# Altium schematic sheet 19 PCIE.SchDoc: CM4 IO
size 297 x 209 mm; Page Create Date: March  8, 1995; Page Number: 19; Page Size: A4; Comment: radxa_1010; Page Count: 19; RevCode: V1.10; Doc: 19 PCIE; DsnPath: D:\WMS\黄工\[RC126]CM4_IO_V1.10\[RC126]_V1.10\CM4 IO_V1.10.DSN; SchematicName: CM4 IO V1.10; PageName: 19 PCIE; PageSize: A4; TopSchematic: True
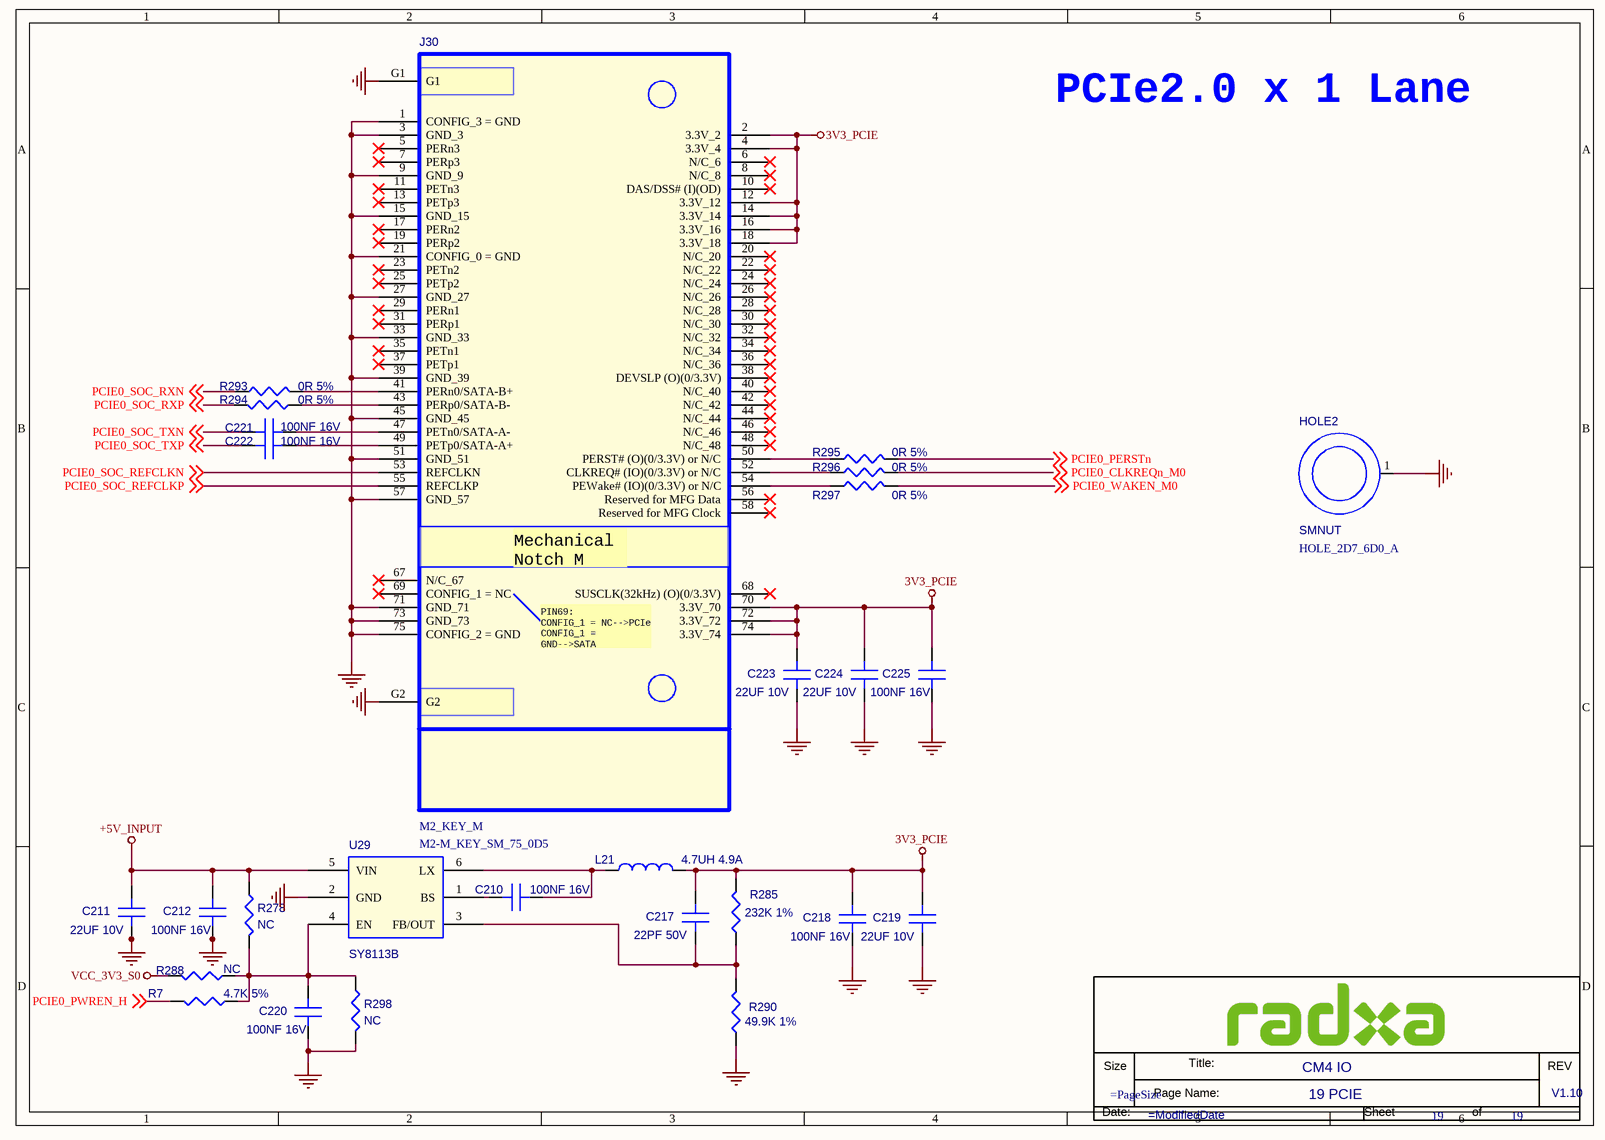
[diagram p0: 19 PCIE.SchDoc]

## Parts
*  Doc: 19 PCIE  RevCode: V1.10  Title: CM4 IO  Page Number: 19  (hidden comment: radxa_1010)  (graphical)
C210  100NF 16V  [C0201]
C211  22UF 10V  [C0603]
C212  100NF 16V  [C0201]
C217  22PF 50V  [C0201]
C218  100NF 16V  [C0201]
C219  22UF 10V  [C0603]
C220  100NF 16V  [C0201]
C221  100NF 16V  [C0201]
C222  100NF 16V  [C0201]
C223  22UF 10V  [C0603]
C224  22UF 10V  [C0603]
C225  100NF 16V  [C0201]
HOLE2  SMNUT  [HOLE_2D7_6D0_A]
J30  M2_KEY_M  [M2-M_KEY_SM_75_0D5]
L21  4.7UH 4.9A  [L_4020]
R7  4.7K 5%  [R0402]
R278  NC  [R0402]
R285  232K 1%  [R0402]
R288  NC  [R0402]
R290  49.9K 1%  [R0402]
R293  0R 5%  [R0402]
R294  0R 5%  [R0402]
R295  0R 5%  [R0402]
R296  0R 5%  [R0402]
R297  0R 5%  [R0402]
R298  NC  [R0402]
U29  SY8113B  [SOT23_6]

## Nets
3V3_PCIE: C217.1(A) C218.1(A) C219.1(A) C223.1(A) C224.1(A) C225.1(A) J30.2(3.3V_2) J30.4(3.3V_4) J30.12(3.3V_12) J30.14(3.3V_14) J30.16(3.3V_16) J30.18(3.3V_18) J30.70(3.3V_70) J30.72(3.3V_72) J30.74(3.3V_74) L21.2 R285.1
+5V_INPUT: C211.1(A) C212.1(A) R278.2 U29.5(VIN)
GND: C211.2(B) C212.2(B) C218.2(B) C219.2(B) C220.2(B) C223.2(B) C224.2(B) C225.2(B) HOLE2.1 J30.1(CONFIG_3_=_GND) J30.3(GND_3) J30.9(GND_9) J30.15(GND_15) J30.21(CONFIG_0_=_GND) J30.27(GND_27) J30.33(GND_33) J30.39(GND_39) J30.45(GND_45) J30.51(GND_51) J30.57(GND_57) J30.71(GND_71) J30.73(GND_73) J30.75(CONFIG_2_=_GND) J30.G1 J30.G2 R290.2 R298.1 U29.2(GND)
VCC_3V3_S0: R288.1
PCIE0_CLKREQn_M0: R296.2 ; off-sheet PCIE0_CLKREQn_M0
PCIE0_PERSTn: R295.2 ; off-sheet PCIE0_PERSTn
PCIE0_PWREN_H: R7.1 ; off-sheet PCIE0_PWREN_H
PCIE0_SOC_REFCLKN: J30.53(REFCLKN) ; off-sheet PCIE0_SOC_REFCLKN
PCIE0_SOC_REFCLKP: J30.55(REFCLKP) ; off-sheet PCIE0_SOC_REFCLKP
PCIE0_SOC_RXN: R293.1 ; off-sheet PCIE0_SOC_RXN
PCIE0_SOC_RXP: R294.1 ; off-sheet PCIE0_SOC_RXP
PCIE0_SOC_TXN: C221.1(A) ; off-sheet PCIE0_SOC_TXN
PCIE0_SOC_TXP: C222.1(A) ; off-sheet PCIE0_SOC_TXP
PCIE0_WAKEN_M0: R297.2 ; off-sheet PCIE0_WAKEN_M0
NetC210_1: C210.1(A) U29.1(BS)
NetC210_2: C210.2(B) L21.1 U29.6(LX)
NetC217_2: C217.2(B) R285.2 R290.1 U29.3(FB/OUT)
NetC220_1: C220.1(A) R7.2 R278.1 R288.2 R298.2 U29.4(EN)
NetC221_2: C221.2(B) J30.47(PETn0/SATA-A-)
NetC222_2: C222.2(B) J30.49(PETp0/SATA-A+)
NetJ30_41: J30.41(PERn0/SATA-B+) R293.2
NetJ30_43: J30.43(PERp0/SATA-B-) R294.2
NetJ30_50: J30.50(PERST#_(O)(0/3.3V)_or_N/C) R295.1
NetJ30_52: J30.52(CLKREQ#_(IO)(0/3.3V)_or_N/C) R296.1
NetJ30_54: J30.54(PEWake#_(IO)(0/3.3V)_or_N/C) R297.1

Not connected (* = marked no-connect by the designer): J30 5(PERn3)* 6(N/C_6)* 7(PERp3)* 8(N/C_8)* 10(DAS/DSS#_(I)(OD))* 11(PETn3)* 13(PETp3)* 17(PERn2)* 19(PERp2)* 20(N/C_20)* 22(N/C_22)* 23(PETn2)* 24(N/C_24)* 25(PETp2)* 26(N/C_26)* 28(N/C_28)* 29(PERn1)* 30(N/C_30)* 31(PERp1)* 32(N/C_32)* 34(N/C_34)* 35(PETn1)* 36(N/C_36)* 37(PETp1)* 38(DEVSLP_(O)(0/3.3V))* 40(N/C_40)* 42(N/C_42)* 44(N/C_44)* 46(N/C_46)* 48(N/C_48)* 56(Reserved_for_MFG_Data)* 58(Reserved_for_MFG_Clock)* 67(N/C_67)* 68(SUSCLK(32kHz)_(O)(0/3.3V))* 69(CONFIG_1_=_NC)*

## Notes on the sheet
- PCIe2.0 x 1 Lane

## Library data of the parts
C210 = C: SMD  0201  100NF  16V  X5R  ±20%  ROHS; PARTS: 1; Part Reference: C210; Part Number: A1C01.00099; OriginalSymbolOrigin: (0,30); PKG_TYPE: CAP2-100-250; LEVEL: STD; PINSWAP: (A,B); Preferred: 6715f349cd0bc5
C211 = C: SMD  0603  22UF  10V  X5R  ±10%  ROHS; PARTS: 1; Part Reference: C211; Part Number: A1C01.00296; OriginalSymbolOrigin: (0,30); PKG_TYPE: CAP2-100-250; LEVEL: STD; PINSWAP: (A,B)
C212 = C: SMD  0201  100NF  16V  X5R  ±20%  ROHS; PARTS: 1; Part Reference: C212; Part Number: A1C01.00099; OriginalSymbolOrigin: (0,30); PKG_TYPE: CAP2-100-250; LEVEL: STD; PINSWAP: (A,B); Preferred: 6715f349cd0bc5
C217 = C: SMD  0201  22PF  50V  NPO  ±5%  ROHS; PARTS: 1; Part Reference: C217; Part Number: A1C01.00021; OriginalSymbolOrigin: (0,30); PKG_TYPE: CAP2-100-250; LEVEL: STD; PINSWAP: (A,B)
C218 = C: SMD  0201  100NF  16V  X5R  ±20%  ROHS; PARTS: 1; Part Reference: C218; Part Number: A1C01.00099; OriginalSymbolOrigin: (0,30); PKG_TYPE: CAP2-100-250; LEVEL: STD; PINSWAP: (A,B); Preferred: 6715f349cd0bc5
C219 = C: SMD  0603  22UF  10V  X5R  ±10%  ROHS; PARTS: 1; Part Reference: C219; Part Number: A1C01.00296; OriginalSymbolOrigin: (0,30); PKG_TYPE: CAP2-100-250; LEVEL: STD; PINSWAP: (A,B)
C220 = C: SMD  0201  100NF  16V  X5R  ±20%  ROHS; PARTS: 1; Part Reference: C220; Part Number: A1C01.00099; OriginalSymbolOrigin: (0,30); PKG_TYPE: CAP2-100-250; LEVEL: STD; PINSWAP: (A,B); Preferred: 6715f349cd0bc5
C221 = C: SMD  0201  100NF  16V  X5R  ±20%  ROHS; PARTS: 1; Part Reference: C221; Part Number: A1C01.00099; OriginalSymbolOrigin: (0,30); PKG_TYPE: CAP2-100-250; LEVEL: STD; PINSWAP: (A,B); Preferred: 6715f349cd0bc5
C222 = C: SMD  0201  100NF  16V  X5R  ±20%  ROHS; PARTS: 1; Part Reference: C222; Part Number: A1C01.00099; OriginalSymbolOrigin: (0,30); PKG_TYPE: CAP2-100-250; LEVEL: STD; PINSWAP: (A,B); Preferred: 6715f349cd0bc5
C223 = C: SMD  0603  22UF  10V  X5R  ±10%  ROHS; PARTS: 1; Part Reference: C223; Part Number: A1C01.00296; OriginalSymbolOrigin: (0,30); PKG_TYPE: CAP2-100-250; LEVEL: STD; PINSWAP: (A,B)
C224 = C: SMD  0603  22UF  10V  X5R  ±10%  ROHS; PARTS: 1; Part Reference: C224; Part Number: A1C01.00296; OriginalSymbolOrigin: (0,30); PKG_TYPE: CAP2-100-250; LEVEL: STD; PINSWAP: (A,B)
C225 = C: SMD  0201  100NF  16V  X5R  ±20%  ROHS; PARTS: 1; Part Reference: C225; Part Number: A1C01.00099; OriginalSymbolOrigin: (0,30); PKG_TYPE: CAP2-100-250; LEVEL: STD; PINSWAP: (A,B); Preferred: 6715f349cd0bc5
HOLE2 = SMNUT: SMD  编带  M2  通孔  一端?5mm  高6.6mm  另一端?2.5mm  高1.5mm  总高8.8mm  (带定位台阶φ2.5mm 高度0.7mm 贴高温胶纸)  适配H8.5高M.2座  铜  镀锡  DDSMT20241011288  ROHS; Part Reference: HOLE2; Part Number: A1S01.00008; Temp Coeff: -40℃ to +150℃; Preferred: 6715f349cd0bc5
J30 = M2_KEY_M: SMD  母座  75PIN  180度  0.5mm脚距  M.2  M KEY  H8.5  黑色  ROHS; Part Reference: J30; Part Number: A1J01.00045; Parameter: 连接器-比派-封装 M2_KEY_M
L21 = L: SMD  带屏蔽  4*4*2mm  4.7UH  4.9A  ±20%  RXWHJ4020-4R7MT  ROHS; Part Reference: L21; Part Number: A1L01.00026
R7 = R: SMD  0201  4.7K  1/20W  ±5%  ROHS; Part Reference: R7; Part Number: A1R01.00014; PCB Footprint: R0201; Preferred: 6715f349cd0bc5; Temp Coeff: -55℃ to +125℃
R278 = R: SMD  0201  10K  1/20W  ±5%  ROHS; Part Reference: R278; Part Number: A1R01.00012; PCB Footprint: R0201; Temp Coeff: －55℃ ~ ＋125℃
R285 = R: SMD  0201  232K  1/20W  ±1%  ROHS; Part Reference: R285; Part Number: A1R01.00189; PCB Footprint: R0201
R288 = R: SMD  0201  10K  1/20W  ±5%  ROHS; Part Reference: R288; Part Number: A1R01.00012; PCB Footprint: R0201; Temp Coeff: －55℃ ~ ＋125℃
R290 = R: SMD  0201  49.9K  1/20W  ±1%  ROHS; Part Reference: R290; Part Number: A1R01.00207; PCB Footprint: R0201
R293 = R: SMD  0201  0R  1/20W  ±5%  ROHS; Part Reference: R293; Part Number: A1R01.00027; PCB Footprint: R0201; Temp Coeff: －55℃ ~ ＋125℃
R294 = R: SMD  0201  0R  1/20W  ±5%  ROHS; Part Reference: R294; Part Number: A1R01.00027; PCB Footprint: R0201; Temp Coeff: －55℃ ~ ＋125℃
R295 = R: SMD  0201  0R  1/20W  ±5%  ROHS; Part Reference: R295; Part Number: A1R01.00027; PCB Footprint: R0201; Temp Coeff: －55℃ ~ ＋125℃
R296 = R: SMD  0201  0R  1/20W  ±5%  ROHS; Part Reference: R296; Part Number: A1R01.00027; PCB Footprint: R0201; Temp Coeff: －55℃ ~ ＋125℃
R297 = R: SMD  0201  0R  1/20W  ±5%  ROHS; Part Reference: R297; Part Number: A1R01.00027; PCB Footprint: R0201; Temp Coeff: －55℃ ~ ＋125℃
R298 = R: SMD  0201  10K  1/20W  ±5%  ROHS; Part Reference: R298; Part Number: A1R01.00012; PCB Footprint: R0201; Temp Coeff: －55℃ ~ ＋125℃
U29 = SY8113B: SMD  DCDC  SY8113BADC  SOT23-6  silergy(矽力杰)  ROHS; Part Reference: U29; Part Number: A1I01.00093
